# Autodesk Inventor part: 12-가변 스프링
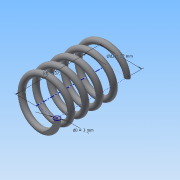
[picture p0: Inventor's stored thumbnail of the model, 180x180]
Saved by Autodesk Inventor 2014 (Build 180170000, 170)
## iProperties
Created: 2015-09
Part Number: 12-가변 스프링
Material: 강철, 탄소
Document SubType Name: Modeling
Designer: study
Density: 1 g/cm^3
Appearance: 반연마
Mass: 2.3997 g
Surface Area: 32.5491 cm^2
Volume: 2.3997 cm^3
Author: study
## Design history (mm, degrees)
sketch "스케치1"
  geometry: L1 (0, 0)-(11, 0); L2 (11, 0)-(11, 36.411); L3 (11, 36.411)-(0, 36.411); L4 (0, 36.411)-(0, 0); C1 r 1.5 at (11, 0)
  constraints: 8 end point, 2 parallel, 1 centre point, 1 coincident, 1 horizontal, 1 perpendicular
  dimensions: "d0" = 3 diameter of C1; "d1" = 36.4112 distance of L3.end L1.start (derived); "d2" = 22 diameter of L2 L4
feature "코일1" sketch "스케치1" pitch "d3" = 10; turns "d5" = 5; dims "d4" = 36.4112 (= d1), "d6" = 0, angle "d7" = 90 deg, angle "d8" = 90 deg, "d9" = 0, "d10" = 0
sketch "스케치2"
  geometry: L1 (-12.5, 0)-(-9.5, 0) reference; 1 further point
  constraints: 1 horizontal alignment
extrude "돌출1" cut sketch "스케치2" stored distance "d11" = 10; taper "d12" = 0 deg
node "작업 평면1"
sketch "스케치3"
  geometry: L1 (-9.5, 0)-(-12.5, 0) reference; 1 further point
  constraints: 1 horizontal alignment
extrude "돌출2" cut sketch "스케치3" stored distance "d14" = 10; taper "d15" = 0 deg
node "솔리드1"
node "절단 모서리 투영1"
node "절단 모서리 투영2"
other parameters: "d13" = 36.4112 (= d1)
